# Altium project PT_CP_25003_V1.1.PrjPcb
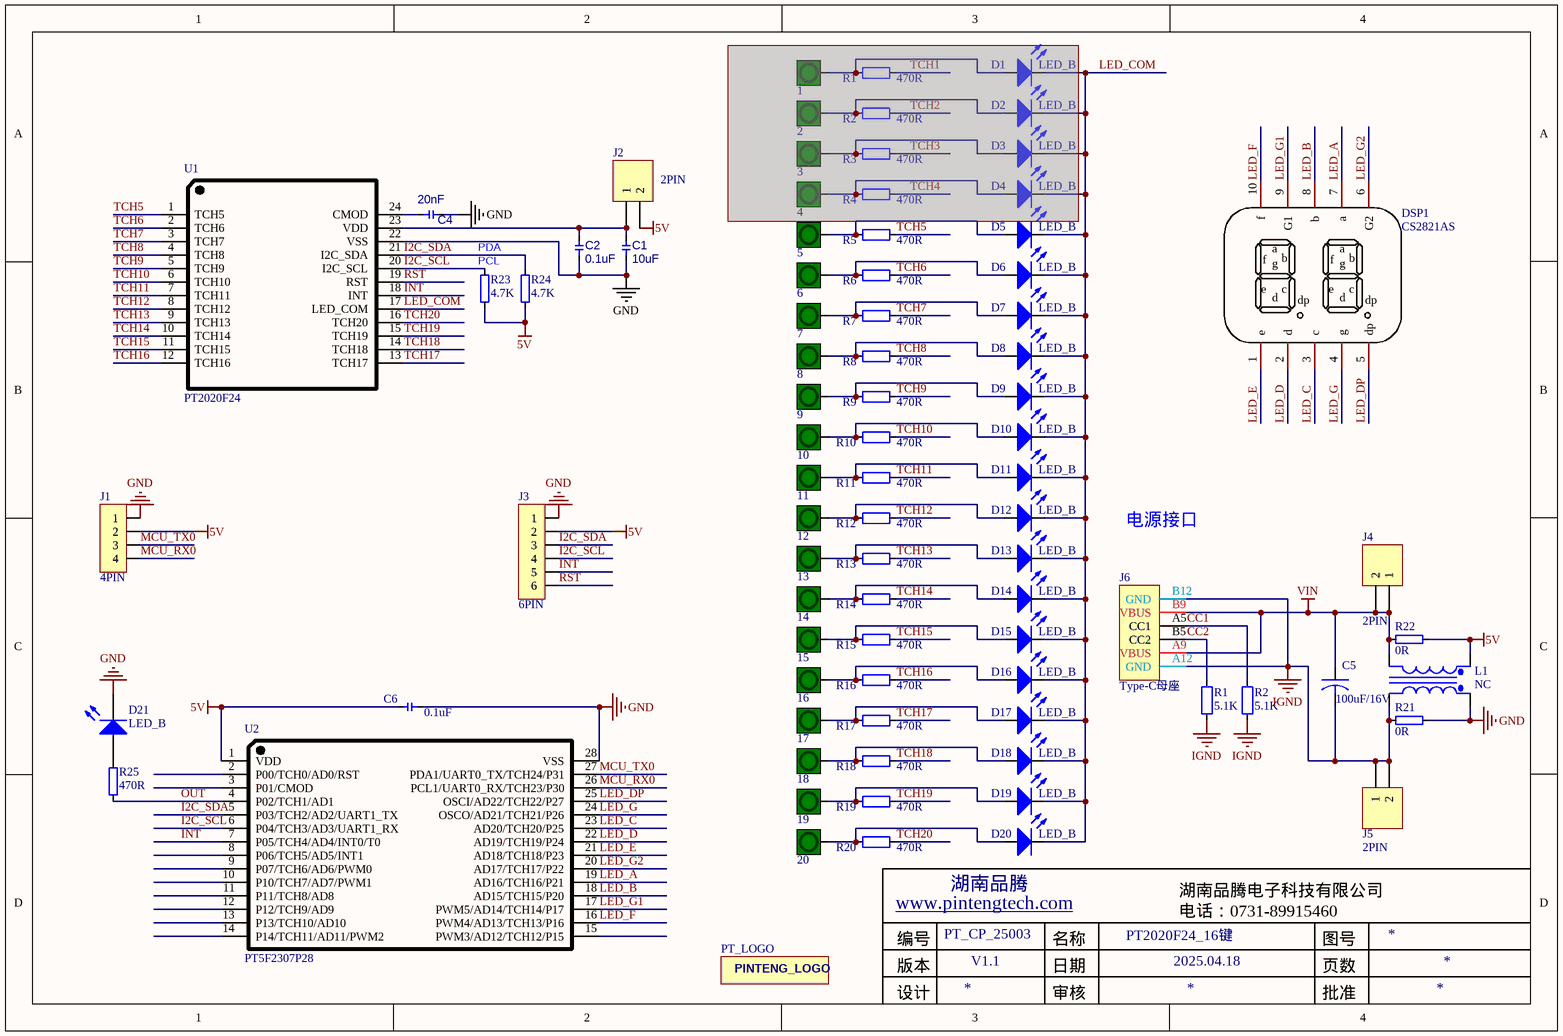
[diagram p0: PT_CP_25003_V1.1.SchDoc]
1 sheet, 84 parts. Net scope: global (net labels, ports and power ports of the same name join across sheets).
Board file: PT_CP_25003_V1.1.PcbDoc

## Sheet PT_CP_25003_V1.1.SchDoc: PT2020F24_16键
size A4; Date: 2025.04.18; DocumentNumber: PT_CP_25003; Revision: V1.1; PageSetup: Record=PageOptions¦CenterHorizontal=True¦CenterVertical=True¦PrintScale=1.00¦XCorrection=1.00¦YCorrection=1.00¦PrintKind=1¦BorderSize=5000000¦LeftOffset=0¦BottomOffset=0¦Orientation=2¦PaperLength=1000¦PaperWidth=1000¦Scale=100¦PaperSource=7¦PrintQuality=1200¦MediaType=1¦DitherType=10¦PrintScaleMode=1¦PaperKind=A4¦PaperIndex=9

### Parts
(Parts that share a designator on the sheet are numbered #1, #2 ... from top to bottom, then left to right.)
1  DOWN  [TP_10mm - H]  (value not drawn)  (masked out: inside a compile mask, not in the netlist)
2  DOWN  [TP_10mm - H]  (value not drawn)  (masked out: inside a compile mask, not in the netlist)
3  DOWN  [TP_10mm - H]  (value not drawn)  (masked out: inside a compile mask, not in the netlist)
4  DOWN  [TP_10mm - H]  (value not drawn)  (masked out: inside a compile mask, not in the netlist)
5  DOWN  [TP_10mm - H]  (value not drawn)
6  DOWN  [TP_10mm - H]  (value not drawn)
7  DOWN  [TP_10mm - H]  (value not drawn)
8  DOWN  [TP_10mm - H]  (value not drawn)
9  DOWN  [TP_10mm - H]  (value not drawn)
10  DOWN  [TP_10mm - H]  (value not drawn)
11  DOWN  [TP_10mm - H]  (value not drawn)
12  DOWN  [TP_10mm - H]  (value not drawn)
13  DOWN  [TP_10mm - H]  (value not drawn)
14  DOWN  [TP_10mm - H]  (value not drawn)
15  DOWN  [TP_10mm - H]  (value not drawn)
16  DOWN  [TP_10mm - H]  (value not drawn)
17  DOWN  [TP_10mm - H]  (value not drawn)
18  DOWN  [TP_10mm - H]  (value not drawn)
19  DOWN  [TP_10mm - H]  (value not drawn)
20  DOWN  [TP_10mm - H]  (value not drawn)
C1  10uF  [C0805]
C2  0.1uF  [C0603]
C4  20nF  [C0603]
C5  100uF/16V  [CS5.0]
C6  0.1uF  [C0603]
D1  LED_B  [LED_0805_F]  (masked out: inside a compile mask, not in the netlist)
D2  LED_B  [LED_0805_F]  (masked out: inside a compile mask, not in the netlist)
D3  LED_B  [LED_0805_F]  (masked out: inside a compile mask, not in the netlist)
D4  LED_B  [LED_0805_F]  (masked out: inside a compile mask, not in the netlist)
D5  LED_B  [LED_0805_F]
D6  LED_B  [LED_0805_F]
D7  LED_B  [LED_0805_F]
D8  LED_B  [LED_0805_F]
D9  LED_B  [LED_0805_F]
D10  LED_B  [LED_0805_F]
D11  LED_B  [LED_0805_F]
D12  LED_B  [LED_0805_F]
D13  LED_B  [LED_0805_F]
D14  LED_B  [LED_0805_F]
D15  LED_B  [LED_0805_F]
D16  LED_B  [LED_0805_F]
D17  LED_B  [LED_0805_F]
D18  LED_B  [LED_0805_F]
D19  LED_B  [LED_0805_F]
D20  LED_B  [LED_0805_F]
D21  LED_B  [LED_0805]
DSP1  CS2821AS  [LED_2_0.28_2281]
J1  4PIN  [D2.54_4P]
J2  2PIN  [D2.54_2P]
J3  6PIN  [D2.54_6P]
J4  2PIN  [D2.54_2P]
J5  2PIN  [D2.54_2P]
J6  Type-C母座  [TYPE-C-6P]
L1  NC  [L_10*5]
PT_LOGO  PT_LOGO  [PT_LOGO_2]  (value not drawn)
R1#1  470R  [RES0603]  (masked out: inside a compile mask, not in the netlist)
R1#2  5.1K  [RES0603]
R2#1  470R  [RES0603]  (masked out: inside a compile mask, not in the netlist)
R2#2  5.1K  [RES0603]
R3  470R  [RES0603]  (masked out: inside a compile mask, not in the netlist)
R4  470R  [RES0603]  (masked out: inside a compile mask, not in the netlist)
R5  470R  [RES0603]
R6  470R  [RES0603]
R7  470R  [RES0603]
R8  470R  [RES0603]
R9  470R  [RES0603]
R10  470R  [RES0603]
R11  470R  [RES0603]
R12  470R  [RES0603]
R13  470R  [RES0603]
R14  470R  [RES0603]
R15  470R  [RES0603]
R16  470R  [RES0603]
R17  470R  [RES0603]
R18  470R  [RES0603]
R19  470R  [RES0603]
R20  470R  [RES0603]
R21  0R  [R0805]
R22  0R  [R0805]
R23  4.7K  [R0603]
R24  4.7K  [R0603]
R25  470R  [R0603]
U1  PT2020F24  [QFN-24_4*4]
U2  PT5F2307P28  [SSOP28_0.635]

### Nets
5V: C6.1 J1.2 J2.2 J3.2 L1.3(Sec+) R22.2 R23.2 R24.2 U2.1(VDD)
GND: C1.2 C2.2 C4.1 C6.2 D21.2(K) J1.1 J3.1 L1.1(Pri+) R21.2 U1.22(VSS) U2.28(VSS)
IGND: C5.2 J5.1 J5.2 J6.A12(GND) J6.B12(GND) L1.2(Pri-) R1#2.1 R2#2.1 R21.1
VIN: C5.1 J4.1 J4.2 J6.A9(VBUS) J6.B9(VBUS) L1.4(Sec-) R22.1
CC1: J6.A5(CC1) R2#2.2
CC2: J6.B5(CC2) R1#2.2
I2C_SCL: J3.4 R23.1 U1.20(I2C_SCL) U2.6(P04/TCH3/AD3/UART1_RX)
I2C_SDA: J3.3 R24.1 U1.21(I2C_SDA) U2.5(P03/TCH2/AD2/UART1_TX)
INT: J3.5 U1.18(INT) U2.7(P05/TCH4/AD4/INT0/T0)
LED_A: DSP1.7(a) U2.19(AD16/TCH16/P21)
LED_B: DSP1.8(b) U2.18(AD15/TCH15/P20)
LED_C: DSP1.3(c) U2.23(AD20/TCH20/P25)
LED_COM: D5.2(K) D6.2(K) D7.2(K) D8.2(K) D9.2(K) D10.2(K) D11.2(K) D12.2(K) D13.2(K) D14.2(K) D15.2(K) D16.2(K) D17.2(K) D18.2(K) D19.2(K) D20.2(K) U1.17(LED_COM)
LED_D: DSP1.2(d) U2.22(AD19/TCH19/P24)
LED_DP: DSP1.5(dp) U2.25(OSCI/AD22/TCH22/P27)
LED_E: DSP1.1(e) U2.21(AD18/TCH18/P23)
LED_F: DSP1.10(f) U2.16(PWM4/AD13/TCH13/P16)
LED_G: DSP1.4(g) U2.24(OSCO/AD21/TCH21/P26)
LED_G1: DSP1.9(G1) U2.17(PWM5/AD14/TCH14/P17)
LED_G2: DSP1.6(G2) U2.20(AD17/TCH17/P22)
MCU_RX0: J1.4 U2.26(PCL1/UART0_RX/TCH23/P30)
MCU_TX0: J1.3 U2.27(PDA1/UART0_TX/TCH24/P31)
OUT: R25.1 U2.4(P02/TCH1/AD1)
RST: J3.6 U1.19(RST)
TCH5: R5.1 U1.1(TCH5)
TCH6: R6.1 U1.2(TCH6)
TCH7: R7.1 U1.3(TCH7)
TCH8: R8.1 U1.4(TCH8)
TCH9: R9.1 U1.5(TCH9)
TCH10: R10.1 U1.6(TCH10)
TCH11: R11.1 U1.7(TCH11)
TCH12: R12.1 U1.8(TCH12)
TCH13: R13.1 U1.9(TCH13)
TCH14: R14.1 U1.10(TCH14)
TCH15: R15.1 U1.11(TCH15)
TCH16: R16.1 U1.12(TCH16)
TCH17: R17.1 U1.13(TCH17)
TCH18: R18.1 U1.14(TCH18)
TCH19: R19.1 U1.15(TCH19)
TCH20: R20.1 U1.16(TCH20)
Net5_1: 5.1 D5.1(A) R5.2
Net6_1: 6.1 D6.1(A) R6.2
Net7_1: 7.1 D7.1(A) R7.2
Net8_1: 8.1 D8.1(A) R8.2
Net9_1: 9.1 D9.1(A) R9.2
Net10_1: 10.1 D10.1(A) R10.2
Net11_1: 11.1 D11.1(A) R11.2
Net12_1: 12.1 D12.1(A) R12.2
Net13_1: 13.1 D13.1(A) R13.2
Net14_1: 14.1 D14.1(A) R14.2
Net15_1: 15.1 D15.1(A) R15.2
Net16_1: 16.1 D16.1(A) R16.2
Net17_1: 17.1 D17.1(A) R17.2
Net18_1: 18.1 D18.1(A) R18.2
Net19_1: 19.1 D19.1(A) R19.2
Net20_1: 20.1 D20.1(A) R20.2
NetC1_1: C1.1 C2.1 J2.1 U1.23(VDD)
NetC4_2: C4.2 U1.24(CMOD)
NetD21_1: D21.1(A) R25.2

Not connected (* = marked no-connect by the designer): U2 2(P00/TCH0/AD0/RST) 3(P01/CMOD) 8(P06/TCH5/AD5/INT1) 9(P07/TCH6/AD6/PWM0) 10(P10/TCH7/AD7/PWM1) 11(P11/TCH8/AD8) 12(P12/TCH9/AD9) 13(P13/TCH10/AD10) 14(P14/TCH11/AD11/PWM2) 15(PWM3/AD12/TCH12/P15)

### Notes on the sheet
- (near R23) PDA
- (near R23) PCL
- 电源接口

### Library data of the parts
1-20 = TOUCH_SM: TP
C1 C2 C4 = CAP3
C5 = CAP2: 电解电容
C6 = CAP1: 电容
D1-D20 = LED0: Typical INFRARED GaAs LED
D21 = LED
DSP1 = LED_2: 2位数码管
J6 = Type-C-receptacle_6p: Type-C 6P直插
L1 = Trans Cupl: Transformer (Coupled Inductor Model)
R1#1 R1#2 R2#1 R2#2 R3-R20 = Res: Resistor
R21-R25 = RES1: 电阻
U1 = PT2020F24: 16键标品
U2 = PT109AP28: MCU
